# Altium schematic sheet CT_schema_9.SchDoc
size 287 x 160 mm
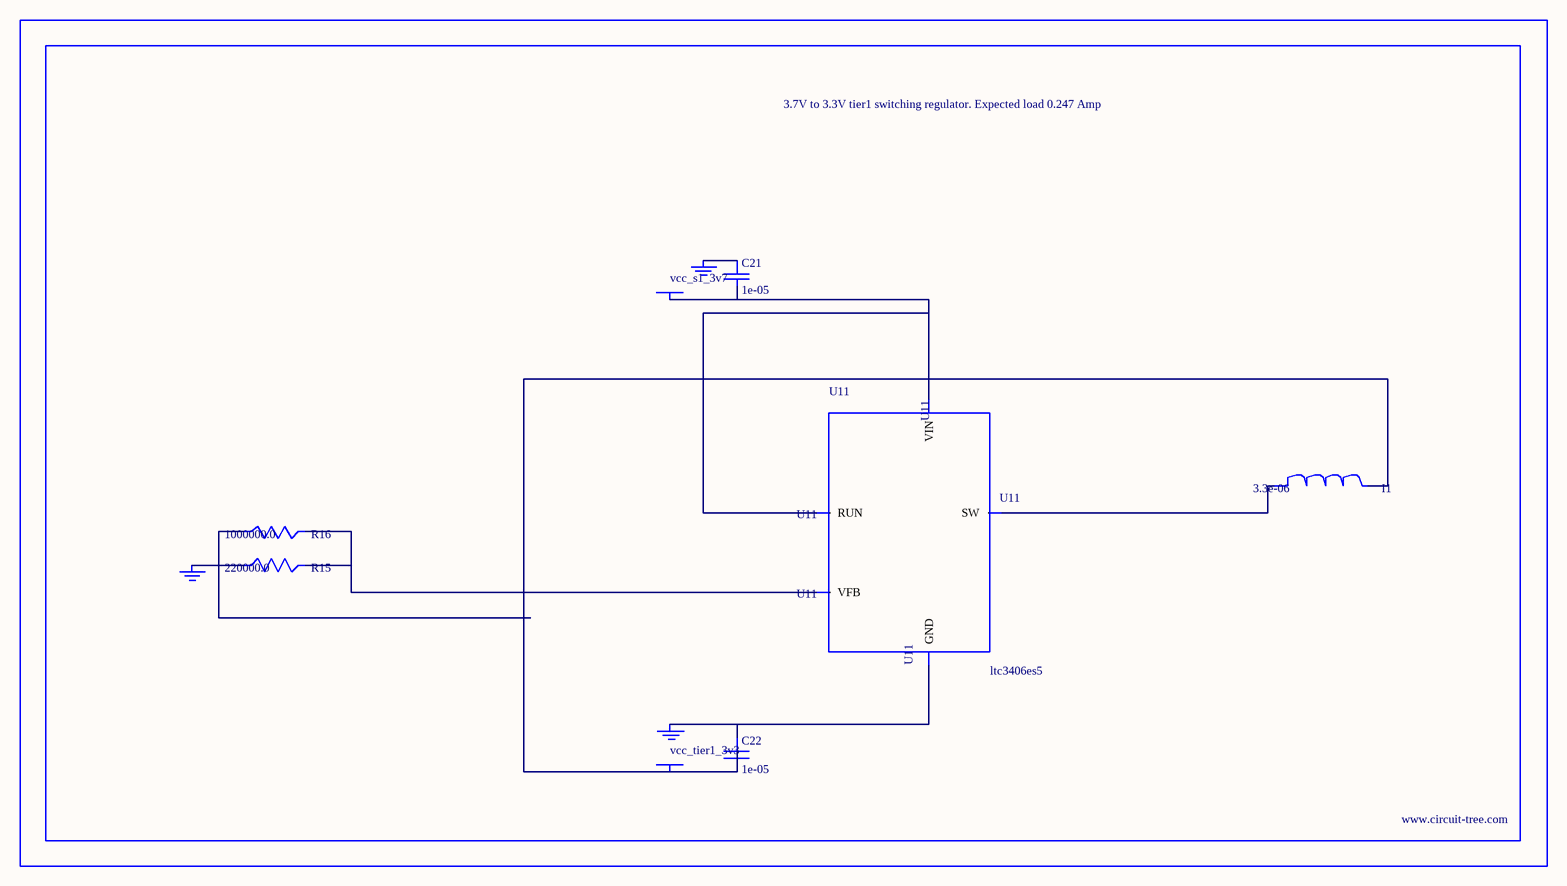
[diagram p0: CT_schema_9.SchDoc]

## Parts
BORDER8  (no value)
C21  1e-05  [C0805]
C22  1e-05  [C0805]
GND_INSTANCE_8_0  (no value)
GND_INSTANCE_8_1  (no value)
GND_INSTANCE_8_2  (no value)
I1  3.3e-06  [L0806]
POWER_INSTANCE_8_0  vcc_tier1_3v3
POWER_INSTANCE_8_1  vcc_s1_3v7
R15  220000.0  [R0603]
R16  1000000.0  [R0603]
U11  ltc3406es5  [TSOT-23-5]

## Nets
NetC21_1: C21.1 GND_INSTANCE_8_1.0(GND)
NetC21_2: C21.2 POWER_INSTANCE_8_1.0(PWR) U11.1(RUN) U11.4(VIN)
NetC22_1: C22.1 GND_INSTANCE_8_0.0(GND) U11.2(GND)
NetC22_2: C22.2 I1.2 POWER_INSTANCE_8_0.0(PWR) R16.1
NetGND_INSTANCE_8_2_0: GND_INSTANCE_8_2.0(GND) R15.1
NetI1_1: I1.1 U11.3(SW)
NetR15_2: R15.2 R16.2 U11.5(VFB)

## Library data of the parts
BORDER8 = BORDER_PAGE8
C21 C22 = C0805C106K8RACTU
GND_INSTANCE_8_0-GND_INSTANCE_8_2 = GND
I1 = L0806C3R3MDWIT
POWER_INSTANCE_8_0 POWER_INSTANCE_8_1 = PWR
R15 = RC0603JR-07220KL
R16 = RC0603JR-071ML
